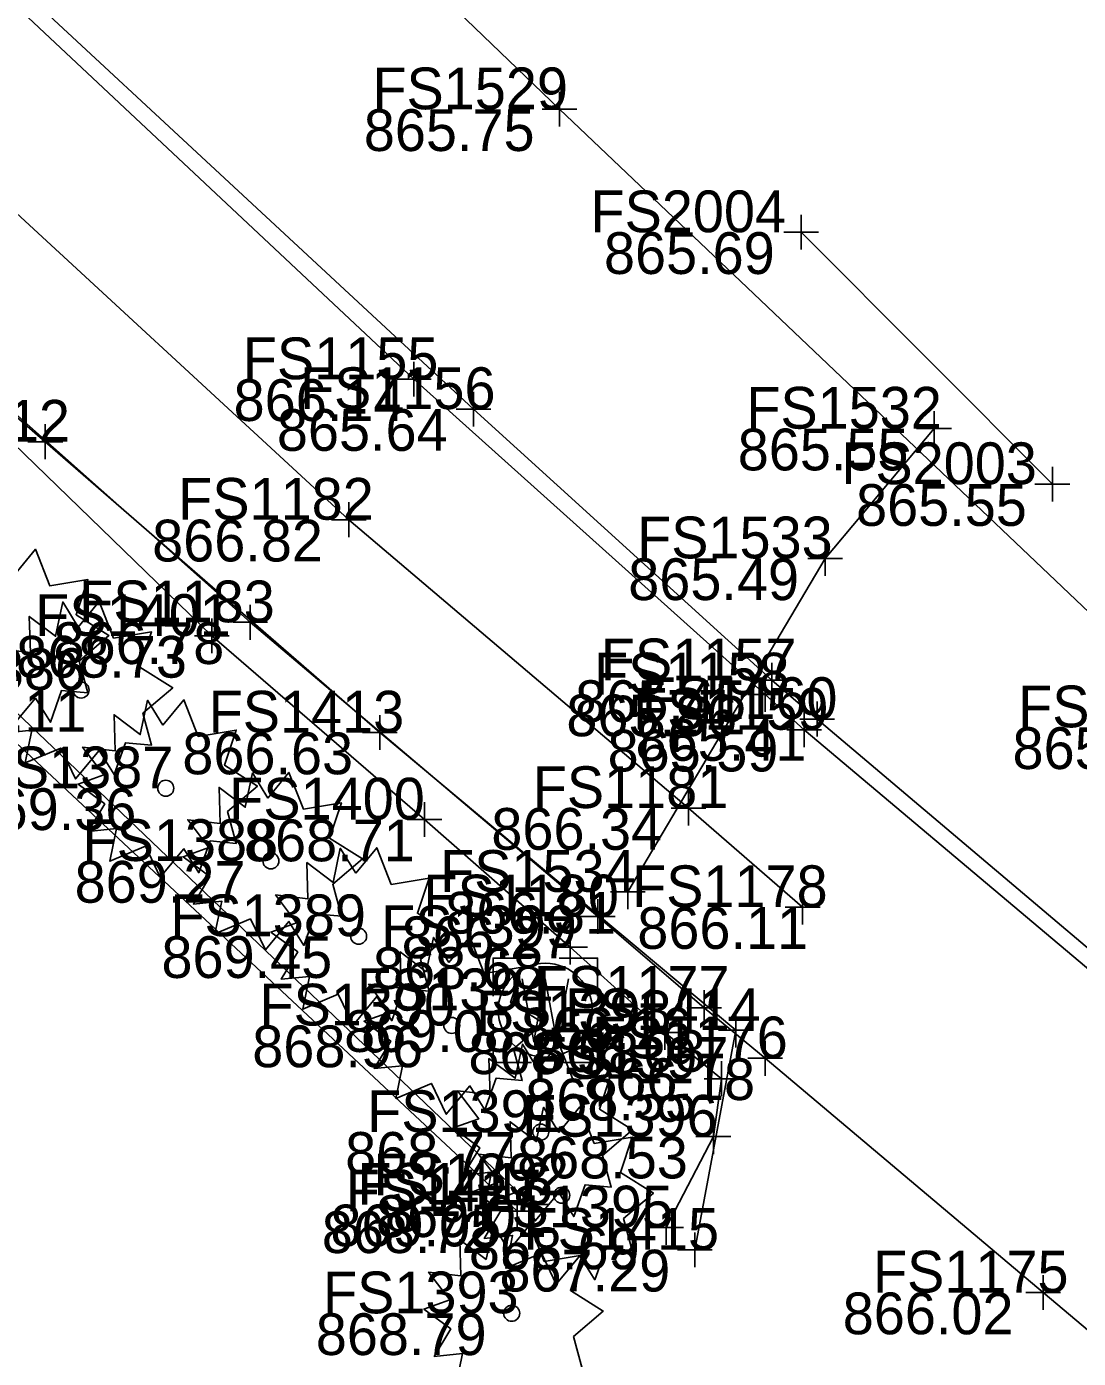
# Model space of a CAD drawing. Extents: x 1479420 to 1479833, y 379731 to 380103.
# Drawn here: x 1479737.84 to 1479768.06, y 379752.4 to 379790.68 of the extents above; entities that cross this region are included whole.
import ezdxf

# ---------------------------------------------------------------- set-up
doc = ezdxf.new("R2010")
doc.units = 0
for name, color, linetype in [('PM_X_Lane_Line', 7, 'Continuous'), ('PV_X_Curb', 7, 'Continuous'), ('PV_X_Walk', 7, 'Continuous'), ('RD_X_Wall', 7, 'Continuous'), ('SV_X_Break_Lines', 7, 'Continuous'), ('SV_X_Shot_Marker', 7, 'Continuous'), ('SV_X_Text_Elevation', 7, 'Continuous'), ('SV_X_Text_Name', 7, 'Continuous'), ('UT_X_Water', 7, 'Continuous'), ('UT_X_Water_Cells', 7, 'Continuous'), ('VG_X_Cells', 7, 'Continuous')]:
    doc.layers.add(name, color=color, linetype=linetype)

msp = doc.modelspace()

# ---------------------------------------------------------------- linework, layer by layer
at = {"layer": 'PM_X_Lane_Line'}
msp.add_line((1479767.317, 379777.532), (1479760.099, 379784.774), dxfattribs=at)
at = {"layer": 'PV_X_Curb'}
for points in [[(1479752.341, 379756.82), (1479734.895, 379773.493), (1479717.229, 379789.662), (1479699.298, 379806.401), (1479688.16, 379794.934), (1479685.526, 379793.897), (1479682.733, 379795.157), (1479681.263, 379797.549), (1479682.493, 379800.746), (1479693.462, 379811.911), (1479675.554, 379828.75), (1479655.832, 379847.057), (1479640.191, 379861.808), (1479628.558, 379849), (1479624.614, 379847.663), (1479622.46, 379848.585), (1479618.996, 379850.857), (1479611.825, 379854.437), (1479601.319, 379856.891), (1479590.521, 379858.038)], [(1479751.933, 379756.628), (1479734.447, 379772.976), (1479716.701, 379789.463), (1479699.4, 379805.742), (1479688.561, 379794.786), (1479685.717, 379793.294), (1479682.291, 379794.8), (1479680.73, 379797.254), (1479682.169, 379801.189), (1479692.652, 379811.907), (1479675.183, 379828.391), (1479655.51, 379846.682), (1479640.151, 379860.926), (1479629.134, 379848.869), (1479624.571, 379847.215), (1479622.228, 379847.911), (1479618.757, 379850.398), (1479611.519, 379853.97), (1479601.347, 379856.369), (1479590.364, 379857.442)], [(1479667.529, 379857.521), (1479681.356, 379844.557), (1479695.384, 379831.416), (1479709.512, 379818.131), (1479724.003, 379804.728), (1479730.662, 379798.272), (1479750.68, 379779.69), (1479759.253, 379771.893), (1479760.555, 379770.78), (1479775.03, 379758.526), (1479788.183, 379747.585), (1479800.537, 379737.251), (1479801.677, 379736.292)], [(1479667.239, 379857.122), (1479681.024, 379844.208), (1479695.135, 379830.978), (1479709.331, 379817.708), (1479723.729, 379804.193), (1479729.719, 379798.6), (1479748.963, 379780.548), (1479759.065, 379771.485), (1479760.185, 379770.473), (1479774.837, 379758.13), (1479787.835, 379747.16), (1479799.962, 379737.109), (1479801.3, 379736.045)]]:
    msp.add_lwpolyline(points, dxfattribs=at)
at = {"layer": 'PV_X_Walk'}
for points in [[(1479760.141, 379765.373), (1479756.862, 379768.221), (1479747.096, 379776.51), (1479736.047, 379786.698), (1479722.324, 379799.574), (1479705.728, 379814.894), (1479685.769, 379833.708), (1479660.411, 379857.395)], [(1479801.031, 379735.954), (1479794.804, 379736.123), (1479792.191, 379733.142), (1479782.769, 379741.06), (1479767.055, 379754.294), (1479759.061, 379761.026), (1479757.309, 379762.481), (1479754.256, 379765.105), (1479744.261, 379773.561), (1479732.859, 379783.688), (1479719.35, 379796.384), (1479703.027, 379811.462), (1479682.443, 379830.686), (1479657.296, 379854.468)]]:
    msp.add_lwpolyline(points, dxfattribs=at)
at = {"layer": 'RD_X_Wall'}
msp.add_lwpolyline([(1479756.217, 379756.164), (1479757.574, 379758.774), (1479757.809, 379760.44), (1479756.184, 379761.773), (1479753.461, 379764.22), (1479749.272, 379767.89), (1479743.159, 379773.169), (1479734.585, 379781.475), (1479724.018, 379791.188), (1479717.004, 379797.909), (1479704.341, 379809.227)], dxfattribs=at)
at = {"layer": 'SV_X_Break_Lines'}
msp.add_lwpolyline([(1479700.791, 379810.474), (1479703.421, 379811.158), (1479704.398, 379810.048), (1479708.429, 379806.713), (1479717.526, 379798.095), (1479729.107, 379786.809), (1479738.375, 379778.753), (1479747.99, 379770.392), (1479758.225, 379761.836), (1479757.039, 379755.523)], dxfattribs=at)
at = {"layer": 'SV_X_Shot_Marker'}
for p, q in [((1479753.15, 379788.809), (1479753.15, 379787.809)), ((1479752.65, 379788.309), (1479753.65, 379788.309)), ((1479753.15, 379788.309), (1479753.15, 379788.309)), ((1479760.099, 379785.274), (1479760.099, 379784.274)), ((1479759.599, 379784.774), (1479760.599, 379784.774)), ((1479760.099, 379784.774), (1479760.099, 379784.774)), ((1479748.963, 379781.048), (1479748.963, 379780.048)), ((1479748.463, 379780.548), (1479749.463, 379780.548)), ((1479748.963, 379780.548), (1479748.963, 379780.548)), ((1479750.68, 379780.19), (1479750.68, 379779.19)), ((1479750.18, 379779.69), (1479751.18, 379779.69)), ((1479750.68, 379779.69), (1479750.68, 379779.69)), ((1479763.916, 379779.628), (1479763.916, 379778.628)), ((1479738.375, 379779.253), (1479738.375, 379778.253)), ((1479763.416, 379779.128), (1479764.416, 379779.128)), ((1479763.916, 379779.128), (1479763.916, 379779.128)), ((1479737.875, 379778.753), (1479738.875, 379778.753)), ((1479738.375, 379778.753), (1479738.375, 379778.753)), ((1479767.317, 379778.032), (1479767.317, 379777.032)), ((1479766.817, 379777.532), (1479767.817, 379777.532)), ((1479767.317, 379777.532), (1479767.317, 379777.532)), ((1479747.096, 379777.01), (1479747.096, 379776.01)), ((1479746.596, 379776.51), (1479747.596, 379776.51)), ((1479747.096, 379776.51), (1479747.096, 379776.51)), ((1479760.787, 379775.899), (1479760.787, 379774.899)), ((1479760.287, 379775.399), (1479761.287, 379775.399)), ((1479760.787, 379775.399), (1479760.787, 379775.399)), ((1479744.261, 379774.061), (1479744.261, 379773.061)), ((1479743.159, 379773.669), (1479743.159, 379772.669)), ((1479743.761, 379773.561), (1479744.761, 379773.561)), ((1479744.261, 379773.561), (1479744.261, 379773.561)), ((1479742.659, 379773.169), (1479743.659, 379773.169)), ((1479743.159, 379773.169), (1479743.159, 379773.169)), ((1479759.253, 379772.393), (1479759.253, 379771.393)), ((1479759.065, 379771.985), (1479759.065, 379770.985)), ((1479758.753, 379771.893), (1479759.753, 379771.893)), ((1479759.253, 379771.893), (1479759.253, 379771.893)), ((1479758.565, 379771.485), (1479759.565, 379771.485)), ((1479759.065, 379771.485), (1479759.065, 379771.485)), ((1479760.555, 379771.28), (1479760.555, 379770.28)), ((1479747.99, 379770.892), (1479747.99, 379769.892)), ((1479760.185, 379770.973), (1479760.185, 379769.973)), ((1479759.685, 379770.473), (1479760.685, 379770.473)), ((1479760.055, 379770.78), (1479761.055, 379770.78)), ((1479760.185, 379770.473), (1479760.185, 379770.473)), ((1479760.555, 379770.78), (1479760.555, 379770.78)), ((1479747.49, 379770.392), (1479748.49, 379770.392)), ((1479747.99, 379770.392), (1479747.99, 379770.392)), ((1479756.862, 379768.721), (1479756.862, 379767.721)), ((1479749.272, 379768.39), (1479749.272, 379767.39)), ((1479756.362, 379768.221), (1479757.362, 379768.221)), ((1479756.862, 379768.221), (1479756.862, 379768.221)), ((1479748.772, 379767.89), (1479749.772, 379767.89)), ((1479749.272, 379767.89), (1479749.272, 379767.89)), ((1479755.114, 379766.312), (1479755.114, 379765.312)), ((1479754.614, 379765.812), (1479755.614, 379765.812)), ((1479755.114, 379765.812), (1479755.114, 379765.812)), ((1479760.141, 379765.873), (1479760.141, 379764.873)), ((1479754.256, 379765.605), (1479754.256, 379764.605)), ((1479753.756, 379765.105), (1479754.756, 379765.105)), ((1479754.256, 379765.105), (1479754.256, 379765.105)), ((1479759.641, 379765.373), (1479760.641, 379765.373)), ((1479760.141, 379765.373), (1479760.141, 379765.373)), ((1479753.461, 379764.72), (1479753.461, 379763.72)), ((1479752.961, 379764.22), (1479753.961, 379764.22)), ((1479753.461, 379764.22), (1479753.461, 379764.22)), ((1479757.309, 379762.981), (1479757.309, 379761.981)), ((1479756.809, 379762.481), (1479757.809, 379762.481)), ((1479757.309, 379762.481), (1479757.309, 379762.481)), ((1479756.184, 379762.273), (1479756.184, 379761.273)), ((1479758.225, 379762.336), (1479758.225, 379761.336)), ((1479755.684, 379761.773), (1479756.684, 379761.773)), ((1479756.184, 379761.773), (1479756.184, 379761.773)), ((1479757.725, 379761.836), (1479758.725, 379761.836)), ((1479758.225, 379761.836), (1479758.225, 379761.836)), ((1479759.061, 379761.526), (1479759.061, 379760.526)), ((1479757.809, 379760.94), (1479757.809, 379759.94)), ((1479758.561, 379761.026), (1479759.561, 379761.026)), ((1479759.061, 379761.026), (1479759.061, 379761.026)), ((1479757.309, 379760.44), (1479758.309, 379760.44)), ((1479757.809, 379760.44), (1479757.809, 379760.44)), ((1479757.574, 379759.274), (1479757.574, 379758.274)), ((1479757.074, 379758.774), (1479758.074, 379758.774)), ((1479757.574, 379758.774), (1479757.574, 379758.774)), ((1479751.933, 379757.128), (1479751.933, 379756.128)), ((1479752.341, 379757.32), (1479752.341, 379756.32)), ((1479751.433, 379756.628), (1479752.433, 379756.628)), ((1479751.841, 379756.82), (1479752.841, 379756.82)), ((1479751.933, 379756.628), (1479751.933, 379756.628)), ((1479752.341, 379756.82), (1479752.341, 379756.82)), ((1479756.217, 379756.664), (1479756.217, 379755.664)), ((1479755.717, 379756.164), (1479756.717, 379756.164)), ((1479756.217, 379756.164), (1479756.217, 379756.164)), ((1479757.039, 379756.023), (1479757.039, 379755.023)), ((1479756.539, 379755.523), (1479757.539, 379755.523)), ((1479757.039, 379755.523), (1479757.039, 379755.523)), ((1479767.055, 379754.794), (1479767.055, 379753.794)), ((1479766.555, 379754.294), (1479767.555, 379754.294)), ((1479767.055, 379754.294), (1479767.055, 379754.294))]:
    msp.add_line(p, q, dxfattribs=at)
at = {"layer": 'UT_X_Water'}
for points in [[(1479473.217, 380054.881), (1479498.741, 380029.974), (1479514.505, 380014.086), (1479533.448, 379996.735), (1479556.003, 379974.319), (1479574.861, 379956.271), (1479584.403, 379947.432), (1479599.597, 379932.819), (1479630.106, 379903.783), (1479644.769, 379889.722), (1479654.209, 379882.356), (1479664.266, 379872.629), (1479692.509, 379845.847), (1479712.672, 379826.686), (1479730.739, 379809.85), (1479753.15, 379788.309), (1479771.842, 379770.542), (1479781.678, 379761.101)], [(1479763.916, 379779.128), (1479760.787, 379775.399), (1479755.114, 379765.812)]]:
    msp.add_lwpolyline(points, dxfattribs=at)
at = {"layer": 'UT_X_Water_Cells'}
msp.add_line((1479752.745, 379762.409), (1479752.745, 379762.409), dxfattribs=at)
for points in [[(1479752.345, 379763.909), (1479751.245, 379763.909), (1479751.245, 379762.809)], [(1479754.245, 379762.809), (1479754.245, 379763.909), (1479753.145, 379763.909)], [(1479752.078, 379763.309), (1479752.412, 379761.509), (1479752.745, 379763.309), (1479753.078, 379761.509), (1479753.412, 379763.309)], [(1479751.245, 379762.009), (1479751.245, 379760.909), (1479752.345, 379760.909)], [(1479753.145, 379760.909), (1479754.245, 379760.909), (1479754.245, 379762.009)]]:
    msp.add_lwpolyline(points, dxfattribs=at)
msp.add_circle((1479752.745, 379762.409), 1.35, dxfattribs=at)
at = {"layer": 'VG_X_Cells'}
for points in [[(1479737.486, 379774.926), (1479738.091, 379775.661), (1479738.506, 379774.607), (1479739.598, 379774.787), (1479739.259, 379773.776), (1479740.204, 379773.181), (1479739.348, 379772.446), (1479739.598, 379771.532), (1479738.844, 379771.601), (1479738.519, 379770.687), (1479738.091, 379771.379), (1479737.413, 379770.562)], [(1479737.013, 379772.8), (1479737.945, 379772.69), (1479737.915, 379773.729), (1479738.668, 379773.16), (1479738.875, 379774.145), (1479739.318, 379773.424)], [(1479739.318, 379773.424), (1479739.923, 379774.159), (1479740.338, 379773.105), (1479741.43, 379773.285), (1479741.091, 379772.274), (1479742.036, 379771.679), (1479741.18, 379770.944), (1479741.43, 379770.03), (1479740.676, 379770.099), (1479740.351, 379769.185), (1479739.923, 379769.877), (1479739.245, 379769.06), (1479738.816, 379769.947), (1479737.796, 379769.517), (1479737.988, 379770.459), (1479737.176, 379770.375)], [(1479741.752, 379770.599), (1479742.357, 379771.334), (1479742.772, 379770.28), (1479743.864, 379770.46), (1479743.525, 379769.449), (1479744.47, 379768.854), (1479743.614, 379768.119), (1479743.864, 379767.205), (1479743.11, 379767.274), (1479742.785, 379766.36), (1479742.357, 379767.052), (1479741.679, 379766.235), (1479741.25, 379767.122), (1479740.23, 379766.692), (1479740.422, 379767.634), (1479739.61, 379767.55), (1479740.084, 379768.34), (1479739.315, 379768.909), (1479740.054, 379769.172), (1479739.447, 379769.975), (1479740.379, 379769.865), (1479740.349, 379770.904), (1479741.102, 379770.335), (1479741.309, 379771.32), (1479741.752, 379770.599)], [(1479744.773, 379768.509), (1479745.378, 379769.244), (1479745.793, 379768.191), (1479746.885, 379768.371), (1479746.546, 379767.359), (1479747.491, 379766.764), (1479746.635, 379766.029), (1479746.885, 379765.116), (1479746.131, 379765.184), (1479745.806, 379764.271), (1479745.378, 379764.963), (1479744.7, 379764.146), (1479744.271, 379765.033), (1479743.251, 379764.603), (1479743.443, 379765.544), (1479742.631, 379765.461), (1479743.105, 379766.251), (1479742.336, 379766.819), (1479743.075, 379767.083), (1479742.468, 379767.886), (1479743.4, 379767.776), (1479743.37, 379768.814), (1479744.123, 379768.246), (1479744.33, 379769.231), (1479744.773, 379768.509)], [(1479747.296, 379766.346), (1479747.901, 379767.081), (1479748.316, 379766.027), (1479749.408, 379766.207), (1479749.069, 379765.196), (1479750.014, 379764.601), (1479749.158, 379763.866), (1479749.408, 379762.952), (1479748.654, 379763.021), (1479748.329, 379762.107), (1479747.901, 379762.799), (1479747.223, 379761.982), (1479746.794, 379762.869), (1479745.774, 379762.439), (1479745.966, 379763.381), (1479745.154, 379763.297), (1479745.628, 379764.087), (1479744.859, 379764.656), (1479745.598, 379764.919), (1479744.991, 379765.722), (1479745.923, 379765.612), (1479745.893, 379766.651), (1479746.646, 379766.082), (1479746.853, 379767.067), (1479747.296, 379766.346)], [(1479749.972, 379763.78), (1479750.577, 379764.515), (1479750.992, 379763.462), (1479752.084, 379763.642), (1479751.745, 379762.63), (1479752.69, 379762.035), (1479751.834, 379761.3), (1479752.084, 379760.387), (1479751.33, 379760.455), (1479751.005, 379759.542), (1479750.577, 379760.234), (1479749.899, 379759.417), (1479749.47, 379760.304), (1479748.45, 379759.874), (1479748.642, 379760.815), (1479747.83, 379760.732), (1479748.304, 379761.522), (1479747.535, 379762.09), (1479748.274, 379762.354), (1479747.667, 379763.157), (1479748.599, 379763.047), (1479748.569, 379764.085), (1479749.322, 379763.517), (1479749.529, 379764.502), (1479749.972, 379763.78)], [(1479752.529, 379760.716), (1479753.134, 379761.451), (1479753.549, 379760.397), (1479754.641, 379760.577), (1479754.302, 379759.566), (1479755.247, 379758.971), (1479754.391, 379758.236), (1479754.641, 379757.322), (1479753.887, 379757.391), (1479753.562, 379756.477), (1479753.134, 379757.169), (1479752.456, 379756.352), (1479752.027, 379757.239), (1479751.007, 379756.809), (1479751.199, 379757.751), (1479750.387, 379757.667), (1479750.861, 379758.457), (1479750.092, 379759.026), (1479750.831, 379759.289), (1479750.224, 379760.092), (1479751.156, 379759.982), (1479751.126, 379761.021), (1479751.879, 379760.452), (1479752.086, 379761.437), (1479752.529, 379760.716)], [(1479753.133, 379758.898), (1479753.738, 379759.633), (1479754.153, 379758.58), (1479755.245, 379758.76), (1479754.906, 379757.748), (1479755.851, 379757.153), (1479754.995, 379756.418), (1479755.245, 379755.505), (1479754.491, 379755.573), (1479754.166, 379754.66), (1479753.738, 379755.351), (1479753.06, 379754.535), (1479752.631, 379755.421), (1479751.611, 379754.991), (1479751.803, 379755.933), (1479750.991, 379755.85), (1479751.465, 379756.64), (1479750.696, 379757.208), (1479751.435, 379757.471), (1479750.828, 379758.275), (1479751.76, 379758.165), (1479751.73, 379759.203), (1479752.483, 379758.635), (1479752.69, 379759.62), (1479753.133, 379758.898)], [(1479751.694, 379755.506), (1479752.299, 379756.241), (1479752.714, 379755.188), (1479753.806, 379755.368), (1479753.467, 379754.356), (1479754.412, 379753.761), (1479753.556, 379753.026), (1479753.806, 379752.113)], [(1479750.172, 379751.599), (1479750.364, 379752.541), (1479749.552, 379752.458), (1479750.026, 379753.248), (1479749.257, 379753.816), (1479749.996, 379754.079), (1479749.389, 379754.883), (1479750.321, 379754.773), (1479750.291, 379755.811), (1479751.044, 379755.243), (1479751.251, 379756.228), (1479751.694, 379755.506)]]:
    msp.add_lwpolyline(points, dxfattribs=at)
for centre in [(1479739.402, 379771.614), (1479741.836, 379768.789), (1479744.857, 379766.7), (1479747.38, 379764.536), (1479750.056, 379761.971), (1479752.613, 379758.906), (1479753.217, 379757.089), (1479751.778, 379753.696)]:
    msp.add_circle(centre, 0.23, dxfattribs=at)

# ---------------------------------------------------------------- texts
at = {"layer": 'SV_X_Text_Elevation'}
for s, p in [('865.75', (1479747.528, 379787.109)), ('865.69', (1479754.43, 379783.574)), ('866.14', (1479743.786, 379779.348)), ('865.64', (1479745.03, 379778.49)), ('865.55', (1479758.275, 379777.928)), ('865.55', (1479761.676, 379776.332)), ('866.82', (1479741.446, 379775.31)), ('865.49', (1479755.128, 379774.199)), ('866.78', (1479738.611, 379772.361)), ('868.73', (1479737.537, 379771.969)), ('869.11', (1479734.65, 379770.414)), ('865.45', (1479753.603, 379770.693)), ('865.86', (1479753.349, 379770.285)), ('865.41', (1479755.339, 379769.58)), ('866.63', (1479742.312, 379769.192)), ('865.59', (1479754.535, 379769.273)), ('865.38', (1479766.173, 379769.342)), ('869.36', (1479736.083, 379767.589)), ('866.34', (1479751.193, 379767.021)), ('868.71', (1479744.084, 379766.69)), ('869.27', (1479739.217, 379765.499)), ('866.31', (1479749.869, 379764.612)), ('866.27', (1479748.615, 379763.905)), ('866.11', (1479755.388, 379764.173)), ('869.45', (1479741.712, 379763.336)), ('868.68', (1479747.792, 379763.02)), ('869.08', (1479746.963, 379761.209)), ('866.16', (1479752.047, 379761.281)), ('868.96', (1479744.322, 379760.77)), ('868.58', (1479750.534, 379760.573)), ('866.08', (1479752.443, 379760.636)), ('866.18', (1479753.865, 379759.826)), ('868.55', (1479752.168, 379759.24)), ('868.77', (1479746.992, 379757.706)), ('868.53', (1479751.933, 379757.574)), ('869.01', (1479747.879, 379755.888)), ('868.72', (1479746.321, 379755.428)), ('869.05', (1479746.568, 379755.62)), ('868.69', (1479750.548, 379754.964)), ('867.29', (1479751.427, 379754.323)), ('866.02', (1479761.292, 379753.094)), ('868.79', (1479746.148, 379752.496))]:
    msp.add_text(s, height=1.2, dxfattribs=at).set_placement(p)
at = {"layer": 'SV_X_Text_Name'}
for s, p in [('FS1529', (1479747.775, 379788.309)), ('FS2004', (1479754.043, 379784.774)), ('FS1155', (1479744.051, 379780.548)), ('FS1156', (1479745.693, 379779.69)), ('FS1532', (1479758.522, 379779.128)), ('FS1412', (1479733.463, 379778.753)), ('FS2003', (1479761.251, 379777.532)), ('FS1182', (1479742.194, 379776.51)), ('FS1533', (1479755.383, 379775.399)), ('FS1183', (1479739.349, 379773.561)), ('FS1401', (1479738.085, 379773.169)), ('FS1157', (1479754.341, 379771.893)), ('FS1386', (1479733.924, 379771.614)), ('FS1158', (1479754.144, 379771.485)), ('FS1160', (1479755.52, 379770.78)), ('FS1413', (1479743.069, 379770.392)), ('FS1159', (1479755.264, 379770.473)), ('FS1530', (1479766.334, 379770.542)), ('FS1387', (1479736.433, 379768.789)), ('FS1181', (1479752.384, 379768.221)), ('FS1400', (1479743.66, 379767.89)), ('FS1388', (1479739.445, 379766.699)), ('FS1534', (1479749.72, 379765.812)), ('FS1178', (1479755.239, 379765.373)), ('FS1180', (1479749.24, 379765.105)), ('FS1389', (1479741.968, 379764.536)), ('FS1399', (1479748.029, 379764.22)), ('FS1394', (1479747.332, 379762.409)), ('FS1177', (1479752.416, 379762.481)), ('FS1390', (1479744.53, 379761.97)), ('FS1398', (1479750.752, 379761.773)), ('FS1414', (1479753.313, 379761.836)), ('FS1176', (1479754.093, 379761.026)), ('FS1397', (1479752.386, 379760.44)), ('FS1391', (1479747.625, 379758.906)), ('FS1396', (1479752.076, 379758.774)), ('FS1392', (1479747.805, 379757.088)), ('FS1417', (1479747.012, 379756.628)), ('FS1416', (1479747.344, 379756.82)), ('FS1395', (1479750.794, 379756.164)), ('FS1415', (1479752.118, 379755.523)), ('FS1175', (1479762.162, 379754.294)), ('FS1393', (1479746.356, 379753.696))]:
    msp.add_text(s, height=1.2, dxfattribs=at).set_placement(p)

doc.saveas('drawing.dxf')
